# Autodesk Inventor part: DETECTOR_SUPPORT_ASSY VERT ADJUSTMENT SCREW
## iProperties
Shininess: 64.0
Length Units: 11272
Angle Units: 11279
Time Units: 11290
Mass Units: 11286
Length Display Precision: 3
Angle Display Precision: 2
Compacted: True
Part Number: DETECTOR_SUPPORT_ASSY VERT ADJUSTMENT SCREW
Document SubType Name: Modeling
Created: 2004-08
Designer: John Blackburn
Material: STAINLESS_STEEL, AUSTENITIC
Manufacturer: Standard
Standards Organization: Custom
Density: 0.0
Volumn: 0.0
Area: 0.0
PropertySet Name: Model Information
Control State: 0
Master: False
Checked Out: False
Author: John Blackburn
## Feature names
1. ExtrusionBlind1
2. ExtrusionBlind2
3. RevolutionAngle1
